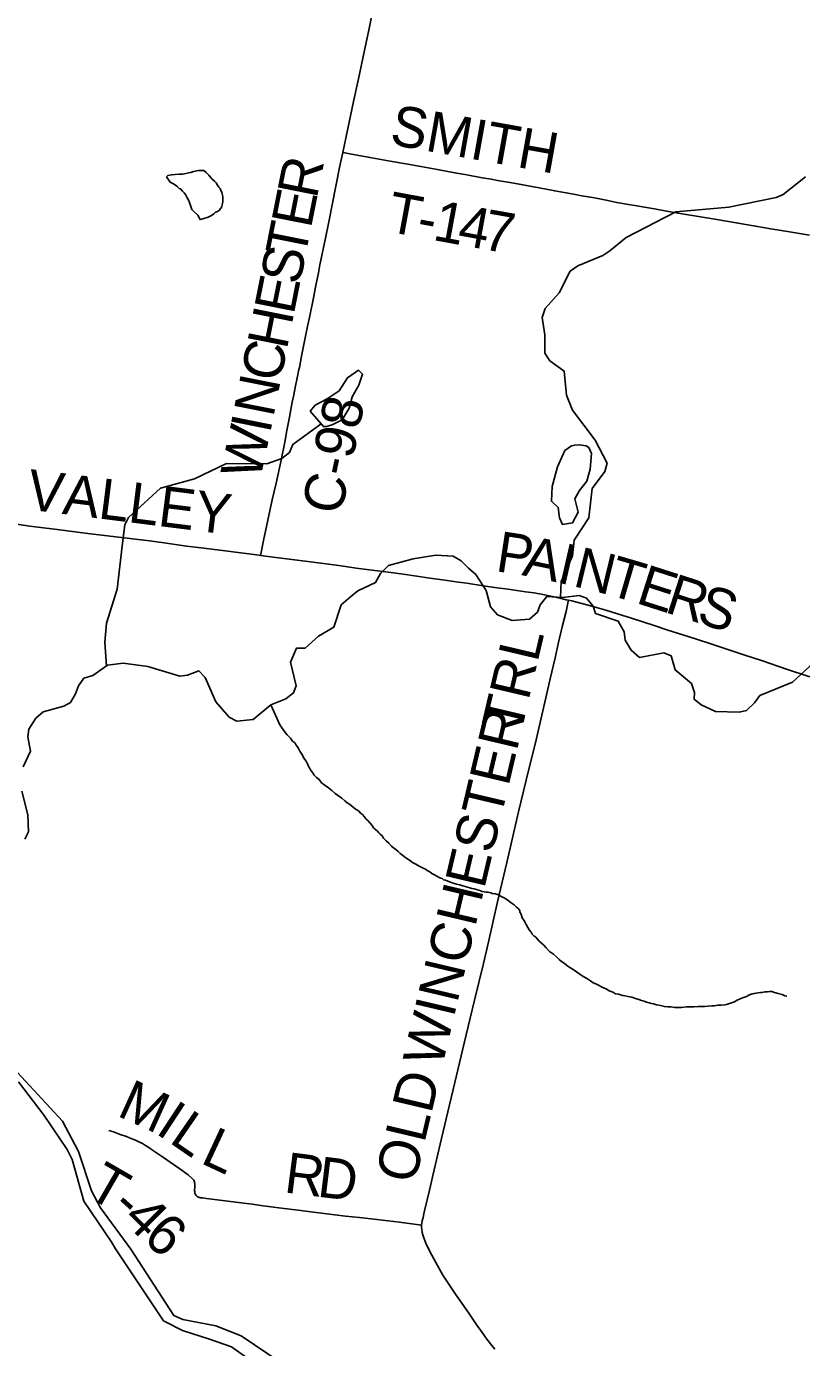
# Model space of a CAD drawing. Extents: x 0 to 34, y 0 to 22.
# Drawn here: x 13.996 to 15.084, y 15.23 to 17.083 of the extents above; entities that cross this region are included whole.
import ezdxf

# ---------------------------------------------------------------- set-up
doc = ezdxf.new("R2010")
doc.units = 0
for name, color, linetype in [('GM_X_County_Road', 7, 'Continuous'), ('GM_X_County_Road_Text', 7, 'Continuous'), ('GM_X_Major_River', 7, 'Continuous'), ('GM_X_Minor_Lake', 7, 'Continuous'), ('GM_X_Minor_River', 7, 'Continuous'), ('GM_X_Township_Road', 7, 'Continuous'), ('GM_X_Township_Road_Text', 7, 'Continuous')]:
    doc.layers.add(name, color=color, linetype=linetype)

msp = doc.modelspace()

# ---------------------------------------------------------------- linework, layer by layer
at = {"layer": 'GM_X_County_Road'}
for points in [[(14.4399, 16.9067), (14.4447, 16.929), (14.455, 16.9779), (14.4618, 17.0101), (14.4699, 17.0477), (14.4764, 17.0781), (14.4788, 17.0897), (14.492, 17.1529), (14.5013, 17.1973), (14.5071, 17.2259), (14.5143, 17.26), (14.5245, 17.3093), (14.5306, 17.3385), (14.5378, 17.3731), (14.5497, 17.4303), (14.5578, 17.468), (14.5635, 17.495), (14.5698, 17.521), (14.5735, 17.5351), (14.5758, 17.5439), (14.5794, 17.557)], [(14.3245, 16.3413), (14.3253, 16.3451), (14.3288, 16.3621), (14.3409, 16.4191), (14.3463, 16.4427), (14.3534, 16.4749), (14.3584, 16.4999), (14.3616, 16.5165), (14.3651, 16.5353), (14.367, 16.5459), (14.3689, 16.5561), (14.3711, 16.5667), (14.3737, 16.5791), (14.3759, 16.5906), (14.3768, 16.5948), (14.378, 16.6002), (14.379, 16.605), (14.3822, 16.6209), (14.3845, 16.6325), (14.3877, 16.6489), (14.3909, 16.6647), (14.3931, 16.675), (14.3986, 16.7024), (14.4022, 16.72), (14.4058, 16.7377), (14.4079, 16.7487), (14.4156, 16.7864), (14.4204, 16.8094), (14.4256, 16.8356), (14.4353, 16.8856), (14.4399, 16.9067)], [(13.8466, 16.4027), (13.8542, 16.4017), (13.8696, 16.3998), (13.8905, 16.397), (13.909, 16.3944), (13.9274, 16.3919), (13.9502, 16.389), (13.9656, 16.3871), (13.9792, 16.3854), (14.0007, 16.3824), (14.0354, 16.378), (14.082, 16.3721), (14.1408, 16.3651), (14.1684, 16.3616), (14.1892, 16.3588), (14.2205, 16.3544), (14.241, 16.3518), (14.2712, 16.348), (14.3225, 16.3416)], [(14.3225, 16.3416), (14.3245, 16.3413), (14.3459, 16.3382), (14.3686, 16.3354), (14.3871, 16.3331), (14.4127, 16.3297), (14.4377, 16.3264), (14.4588, 16.3235), (14.481, 16.3207), (14.5043, 16.3177), (14.5247, 16.3147), (14.5438, 16.312), (14.5622, 16.3095), (14.5801, 16.3069), (14.6022, 16.3037), (14.6139, 16.3021), (14.6372, 16.2987), (14.6569, 16.2959), (14.6721, 16.2938), (14.6842, 16.292), (14.6967, 16.2903), (14.7088, 16.2885), (14.7206, 16.2864), (14.7322, 16.284), (14.7429, 16.2816), (14.7537, 16.2791), (14.7568, 16.2784)], [(14.7568, 16.2784), (14.7614, 16.2773), (14.7739, 16.274), (14.7896, 16.27), (14.8092, 16.2644), (14.8318, 16.2573), (14.8454, 16.253), (14.8773, 16.2427), (14.895, 16.237), (14.9353, 16.224), (14.9579, 16.2166), (14.985, 16.2077), (15.0031, 16.2018), (15.029, 16.1932), (15.0402, 16.1895), (15.0613, 16.1823), (15.0958, 16.171)]]:
    msp.add_lwpolyline(points, dxfattribs=at)
at = {"layer": 'GM_X_Major_River'}
for points in [[(13.9772, 15.6224), (14.0462, 15.5474), (14.0691, 15.5047), (14.0873, 15.4499), (14.0996, 15.4257), (14.1424, 15.3677)], [(13.9847, 15.6028), (14.0205, 15.5556), (14.0532, 15.5077), (14.0598, 15.4939), (14.0763, 15.435), (14.1149, 15.3786), (14.1207, 15.3682), (14.1884, 15.2674), (14.215, 15.2538), (14.2528, 15.2416), (14.2837, 15.231), (14.3536, 15.1811)], [(14.1424, 15.3677), (14.2026, 15.2746), (14.2154, 15.2694), (14.2619, 15.2604), (14.2973, 15.2462), (14.3883, 15.1848)]]:
    msp.add_lwpolyline(points, dxfattribs=at)
at = {"layer": 'GM_X_Minor_Lake'}
for points in [[(14.1925, 16.8723), (14.1929, 16.8727), (14.1944, 16.8742), (14.1994, 16.8753), (14.2047, 16.8757), (14.2104, 16.876), (14.215, 16.8763), (14.2195, 16.8771), (14.2233, 16.8778), (14.2268, 16.8785), (14.2302, 16.8797), (14.2329, 16.8804), (14.2352, 16.8808), (14.2374, 16.8811), (14.2405, 16.8815), (14.2431, 16.8815), (14.245, 16.8815), (14.2481, 16.8784), (14.2518, 16.8746), (14.256, 16.8696), (14.2598, 16.8665), (14.262, 16.8638), (14.2639, 16.8608), (14.2658, 16.8581), (14.2677, 16.8558), (14.2688, 16.8532), (14.2699, 16.8509), (14.2714, 16.8444), (14.2714, 16.8398), (14.2717, 16.8379), (14.271, 16.8349), (14.2706, 16.833), (14.2702, 16.8303), (14.2683, 16.8281), (14.2667, 16.8258), (14.264, 16.8239), (14.2614, 16.8228), (14.2591, 16.8205), (14.2556, 16.8183), (14.2511, 16.8157), (14.245, 16.8138), (14.2419, 16.8131), (14.2396, 16.8123), (14.2363, 16.8184), (14.2306, 16.8238), (14.2279, 16.8265), (14.2268, 16.8307), (14.2253, 16.8348), (14.2242, 16.8379), (14.2235, 16.8398), (14.2212, 16.844), (14.219, 16.8474), (14.2171, 16.8501), (14.2148, 16.8524), (14.2122, 16.8555), (14.2103, 16.8562), (14.2069, 16.8593), (14.2038, 16.8616), (14.2012, 16.8628), (14.1993, 16.8639), (14.1974, 16.8651), (14.1925, 16.8723)], [(14.4262, 16.5249), (14.4393, 16.5315), (14.4491, 16.5476), (14.4529, 16.5638), (14.4623, 16.5799), (14.4676, 16.5954), (14.462, 16.6012), (14.4466, 16.5906), (14.4348, 16.5719), (14.4179, 16.5609), (14.4014, 16.5521), (14.394, 16.5436)], [(14.394, 16.5436), (14.4128, 16.522), (14.4175, 16.522), (14.4262, 16.5249)], [(14.761, 16.4951), (14.7518, 16.4885), (14.7414, 16.4655), (14.734, 16.438), (14.7328, 16.4171), (14.7425, 16.4085), (14.7444, 16.394), (14.7484, 16.3848), (14.7625, 16.3868), (14.7704, 16.4018), (14.7659, 16.4205), (14.7722, 16.4321), (14.7827, 16.4452), (14.7873, 16.4622), (14.7892, 16.4842), (14.7856, 16.4926)], [(14.7856, 16.4926), (14.7815, 16.4949), (14.7722, 16.4965), (14.7657, 16.496), (14.761, 16.4951)]]:
    msp.add_lwpolyline(points, dxfattribs=at)
at = {"layer": 'GM_X_Minor_River'}
for points in [[(14.7454, 16.2824), (14.7467, 16.3047), (14.7627, 16.3408), (14.7646, 16.3624), (14.7854, 16.3938), (14.7901, 16.4351), (14.8077, 16.459), (14.811, 16.4708), (14.7942, 16.5031), (14.7625, 16.5448), (14.7542, 16.5659), (14.7507, 16.5998), (14.7306, 16.6143), (14.7236, 16.6251), (14.7237, 16.6506), (14.7197, 16.675), (14.7242, 16.6878), (14.7436, 16.7094), (14.759, 16.7398), (14.7698, 16.7475), (14.8051, 16.7619), (14.8147, 16.7685), (14.8379, 16.7873), (14.9077, 16.8233), (14.9818, 16.8299), (15.0485, 16.8436), (15.0581, 16.8475), (15.0897, 16.8722)], [(14.1081, 16.1859), (14.1059, 16.2194), (14.108, 16.2463), (14.1234, 16.2938), (14.1305, 16.3582), (14.1341, 16.384), (14.1392, 16.3945), (14.1841, 16.4356), (14.2318, 16.4486), (14.2767, 16.4703), (14.3332, 16.4698), (14.3543, 16.4772), (14.3651, 16.4857), (14.3699, 16.497), (14.4094, 16.5259)], [(13.9914, 16.0446), (14.0017, 16.0664), (13.9979, 16.0867), (13.9993, 16.0973), (14.0091, 16.113), (14.0192, 16.1219), (14.0482, 16.1296), (14.0578, 16.135), (14.0645, 16.147), (14.0689, 16.1583), (14.0764, 16.1692), (14.089, 16.1727), (14.1098, 16.187), (14.1314, 16.1899), (14.1663, 16.1853), (14.2111, 16.1717), (14.2218, 16.173), (14.2378, 16.1795), (14.2467, 16.1698), (14.2619, 16.1356), (14.2805, 16.1143), (14.2913, 16.1087), (14.3142, 16.1108), (14.3389, 16.1315), (14.3599, 16.1401), (14.3707, 16.1482), (14.3744, 16.1584), (14.3667, 16.1913), (14.3751, 16.2112), (14.3869, 16.2113), (14.4058, 16.228), (14.4274, 16.2404), (14.4375, 16.2717), (14.4507, 16.2831), (14.4611, 16.2913), (14.486, 16.3032), (14.4931, 16.316), (14.5043, 16.3271), (14.5387, 16.3365), (14.5707, 16.3415), (14.5949, 16.3402), (14.6062, 16.3338), (14.6166, 16.3233), (14.6266, 16.3144), (14.6413, 16.292), (14.6473, 16.269), (14.6573, 16.2578), (14.6776, 16.2497), (14.7019, 16.2518), (14.7135, 16.2618), (14.7172, 16.272), (14.7265, 16.2835), (14.7489, 16.2823), (14.7717, 16.2848), (14.7822, 16.2811), (14.7915, 16.2699), (14.7947, 16.2599), (14.8267, 16.2489), (14.8351, 16.2339), (14.8364, 16.2221), (14.8448, 16.2082), (14.8567, 16.1981), (14.8906, 16.2045), (14.9008, 16.2004), (14.9068, 16.1809), (14.9296, 16.1614), (14.9339, 16.1491), (14.9333, 16.1393), (14.943, 16.1315), (14.9633, 16.1222), (14.9966, 16.1211), (15.0069, 16.1235), (15.0178, 16.1346), (15.0256, 16.1447), (15.0715, 16.1634), (15.1304, 16.2175)], [(14.3389, 16.1315), (14.3516, 16.1037), (14.3591, 16.0927), (14.3618, 16.0896), (14.3648, 16.0865), (14.3667, 16.085), (14.3693, 16.0808), (14.372, 16.0789), (14.3735, 16.077), (14.3746, 16.0751), (14.3765, 16.0728), (14.378, 16.0701), (14.3795, 16.0667), (14.3814, 16.0636), (14.3833, 16.0609), (14.3848, 16.0579), (14.3866, 16.0548), (14.3885, 16.0525), (14.3904, 16.0487), (14.3912, 16.0464), (14.3923, 16.0445), (14.3938, 16.0422), (14.3945, 16.0403), (14.3975, 16.0365), (14.3998, 16.0331), (14.4032, 16.0296), (14.4066, 16.0269), (14.41, 16.0223), (14.4153, 16.0185), (14.4198, 16.0151), (14.4248, 16.0116), (14.4293, 16.0074), (14.4338, 16.0039), (14.4388, 16.0005), (14.4429, 15.997), (14.4463, 15.9943), (14.4493, 15.9924), (14.4524, 15.9901), (14.4546, 15.9878), (14.458, 15.9851), (14.4607, 15.9836), (14.463, 15.9817), (14.4648, 15.9798), (14.4675, 15.9775), (14.4701, 15.9748), (14.4728, 15.9713), (14.475, 15.9694), (14.4811, 15.9622), (14.4833, 15.9591), (14.4864, 15.9564), (14.4886, 15.9545), (14.4905, 15.9522), (14.4924, 15.9503), (14.4951, 15.948), (14.4973, 15.9446), (14.5007, 15.9407), (14.5045, 15.9373), (14.5083, 15.9334), (14.5113, 15.9308), (14.5143, 15.9288), (14.5177, 15.9258), (14.5207, 15.9231), (14.5241, 15.92), (14.5287, 15.917), (14.5336, 15.9135), (14.5378, 15.9104), (14.5423, 15.9081), (14.5472, 15.9054), (14.551, 15.9035), (14.5537, 15.902), (14.5563, 15.9008), (14.5582, 15.8993), (14.562, 15.8973), (14.565, 15.895), (14.5688, 15.8931), (14.5722, 15.8912), (14.5753, 15.8893), (14.5775, 15.8885), (14.5794, 15.8877), (14.5813, 15.8862), (14.584, 15.8854), (14.5866, 15.8846), (14.5897, 15.8831), (14.595, 15.8815), (14.5995, 15.88), (14.6045, 15.8788), (14.6083, 15.8776), (14.6117, 15.8765), (14.6151, 15.8757), (14.6185, 15.8749), (14.6212, 15.8737), (14.6242, 15.8733), (14.6276, 15.8725), (14.631, 15.8714), (14.6356, 15.8698), (14.6413, 15.8686), (14.6439, 15.8686), (14.6477, 15.8678), (14.6496, 15.8671), (14.6542, 15.8663), (14.6569, 15.8655)], [(13.9934, 15.9432), (13.9985, 15.9533), (13.9979, 15.9772), (13.9895, 16.0105)], [(14.6569, 15.8655), (14.6588, 15.8655), (14.6625, 15.8628), (14.6675, 15.8601), (14.672, 15.857), (14.6765, 15.8539), (14.6807, 15.8509), (14.6837, 15.8478), (14.686, 15.8459), (14.6883, 15.8428), (14.6886, 15.8409), (14.6898, 15.8386), (14.6909, 15.836), (14.692, 15.8325), (14.6943, 15.8295), (14.6961, 15.8264), (14.6973, 15.8234), (14.6999, 15.8192), (14.7018, 15.8157), (14.7044, 15.8127), (14.7059, 15.81), (14.7082, 15.8073), (14.7108, 15.8054), (14.7131, 15.8027), (14.7157, 15.8001), (14.7191, 15.7974), (14.7222, 15.7943), (14.7256, 15.7905), (14.7301, 15.7855), (14.7358, 15.7817), (14.7399, 15.7782), (14.7437, 15.7744), (14.7471, 15.7717), (14.7509, 15.769), (14.7547, 15.7659), (14.7588, 15.7629), (14.7634, 15.7602), (14.7774, 15.7506), (14.7834, 15.7471), (14.7876, 15.7444), (14.7914, 15.7417), (14.7952, 15.7402), (14.799, 15.7383), (14.8024, 15.7363), (14.8058, 15.7344), (14.8096, 15.7329), (14.813, 15.7306), (14.8168, 15.7294), (14.8202, 15.7278), (14.8228, 15.7263), (14.827, 15.7255), (14.8297, 15.7247), (14.8331, 15.7239), (14.8361, 15.7232), (14.8403, 15.7224), (14.8456, 15.7212), (14.8509, 15.7196), (14.8555, 15.7181), (14.8593, 15.7169), (14.8631, 15.7158), (14.8665, 15.7146), (14.8703, 15.7134), (14.8733, 15.7126), (14.8764, 15.7119), (14.8802, 15.7107), (14.884, 15.7103), (14.8878, 15.7095), (14.8915, 15.7083), (14.8961, 15.7079), (14.9007, 15.7079), (14.9056, 15.7071), (14.9105, 15.7071), (14.9155, 15.707), (14.9223, 15.7077), (14.9277, 15.7077), (14.933, 15.708), (14.9387, 15.7084), (14.9436, 15.7083), (14.9482, 15.7083), (14.9531, 15.709), (14.9581, 15.7094), (14.9619, 15.7093), (14.9665, 15.7101), (14.971, 15.7104), (14.9763, 15.7108), (14.9786, 15.7111), (14.9817, 15.7119), (14.9897, 15.7149), (14.9935, 15.7171), (14.9977, 15.719), (15.0011, 15.7205), (15.0038, 15.7216), (15.0057, 15.722), (15.011, 15.7246), (15.0145, 15.7261), (15.0179, 15.7268), (15.0202, 15.7272), (15.0232, 15.7275), (15.0263, 15.7279), (15.0286, 15.7279), (15.0308, 15.7286)], [(15.0308, 15.7286), (15.0327, 15.729), (15.0362, 15.729), (15.0392, 15.7293), (15.0423, 15.7293), (15.046, 15.7281), (15.0514, 15.7266), (15.0567, 15.725), (15.0608, 15.7231), (15.0631, 15.7227), (15.0635, 15.7227)]]:
    msp.add_lwpolyline(points, dxfattribs=at)
at = {"layer": 'GM_X_Township_Road'}
for points in [[(14.4399, 16.9067), (14.4428, 16.9061), (14.4498, 16.9048), (14.4627, 16.9024), (14.4809, 16.8991), (14.5066, 16.8945), (14.5311, 16.8902), (14.5494, 16.887), (14.5751, 16.8822), (14.5973, 16.8782), (14.6142, 16.875), (14.6356, 16.8712), (14.6482, 16.869), (14.6573, 16.8674), (14.6803, 16.8633), (14.7157, 16.8568), (14.7376, 16.8526), (14.7639, 16.8479), (14.7755, 16.8458), (14.7932, 16.8427), (14.8096, 16.8396), (14.8249, 16.8366), (14.8413, 16.8336), (14.853, 16.8317), (14.8634, 16.8299), (14.8777, 16.8273), (14.8946, 16.8244), (14.9166, 16.8204), (14.9649, 16.8127), (14.9924, 16.808), (15.0195, 16.8033), (15.0408, 16.7996), (15.0671, 16.7952), (15.0951, 16.7905)], [(14.5506, 15.4017), (14.5516, 15.4076), (14.5527, 15.4122), (14.5539, 15.4173), (14.5549, 15.4215), (14.5618, 15.4506), (14.5669, 15.473), (14.5715, 15.493), (14.5786, 15.523), (14.59, 15.5706), (14.5972, 15.6016), (14.6102, 15.6569), (14.6188, 15.6921), (14.625, 15.7174), (14.6375, 15.7688), (14.645, 15.8009), (14.6571, 15.855), (14.6704, 15.9102), (14.6867, 15.9815), (14.6975, 16.0258), (14.7113, 16.0824), (14.7234, 16.1354), (14.7311, 16.1682), (14.738, 16.1976), (14.7424, 16.217), (14.7486, 16.2428), (14.7534, 16.2626), (14.7559, 16.274), (14.7568, 16.2784)], [(14.1114, 15.5345), (14.1179, 15.5323), (14.1274, 15.5289), (14.1361, 15.5258), (14.1405, 15.524), (14.1453, 15.5222), (14.1489, 15.5206), (14.1538, 15.5184), (14.1588, 15.5159), (14.163, 15.5134), (14.1675, 15.5104), (14.1728, 15.5067), (14.1868, 15.4973), (14.2039, 15.4859), (14.2113, 15.4805), (14.2227, 15.4722), (14.2284, 15.4672), (14.2295, 15.4662), (14.2301, 15.4655), (14.2306, 15.4646), (14.2311, 15.4635), (14.2316, 15.4622), (14.2319, 15.4612), (14.2321, 15.46), (14.2322, 15.4586), (14.2322, 15.4566), (14.2321, 15.4541), (14.2319, 15.4511), (14.2319, 15.4499), (14.232, 15.4485), (14.2321, 15.4475), (14.2324, 15.4465), (14.2327, 15.4457), (14.2332, 15.4447), (14.2337, 15.4439), (14.2343, 15.4431), (14.235, 15.4422), (14.2356, 15.4416), (14.2363, 15.4411), (14.2373, 15.4407), (14.2381, 15.4404), (14.2391, 15.4402), (14.24, 15.44), (14.2433, 15.4397), (14.2486, 15.439), (14.2973, 15.433), (14.3129, 15.431), (14.3282, 15.4288), (14.354, 15.4255), (14.3773, 15.4225), (14.3989, 15.4198), (14.4211, 15.4169), (14.4439, 15.4143), (14.4636, 15.4121), (14.4878, 15.4095), (14.5198, 15.4056), (14.5506, 15.4017)], [(14.6534, 15.2276), (14.6492, 15.2328), (14.6422, 15.2416), (14.6355, 15.2511), (14.6273, 15.2627), (14.6168, 15.2779), (14.5984, 15.3046), (14.5805, 15.3315), (14.5708, 15.349), (14.562, 15.3648), (14.5564, 15.3761), (14.5536, 15.3836), (14.5523, 15.3878), (14.5515, 15.3913), (14.5507, 15.3961), (14.5505, 15.3988), (14.5506, 15.4017)]]:
    msp.add_lwpolyline(points, dxfattribs=at)

# ---------------------------------------------------------------- texts
at = {"layer": 'GM_X_County_Road_Text'}
for s, height, rotation, p in [('R', 0.0568, 78.6901, (14.4033, 16.8403)), ('E', 0.0568, 78.7556, (14.3951, 16.7987)), ('T', 0.0568, 78.7556, (14.3868, 16.757)), ('S', 0.0568, 78.7548, (14.3793, 16.7194)), ('E', 0.0568, 78.7556, (14.371, 16.6777)), ('H', 0.0568, 78.7594, (14.3613, 16.6287)), ('C', 0.0568, 78.7583, (14.3522, 16.5829)), ('N', 0.0568, 78.7532, (14.3424, 16.5338)), ('C-98', 0.05682, 78.1627, (14.4374, 16.3963)), ('I', 0.0568, 78.694, (14.3378, 16.5109)), ('W', 0.0568, 77.6512, (14.3235, 16.4455)), ('VALLEY', 0.05682, 352.8322, (13.9946, 16.406)), ('P', 0.0568, 351.3696, (14.6531, 16.3193)), ('A', 0.0568, 348.3861, (14.6903, 16.3137)), ('I', 0.0568, 347.1016, (14.7389, 16.3037)), ('N', 0.0568, 346.3039, (14.7615, 16.2985)), ('T', 0.0568, 343.6743, (14.8094, 16.2869)), ('E', 0.0568, 342.2745, (14.8498, 16.275)), ('R', 0.0568, 342.1822, (14.8903, 16.2621)), ('S', 0.0568, 342.1814, (14.9347, 16.2478))]:
    msp.add_text(s, height=height, rotation=rotation, dxfattribs=at).set_placement(p)
at = {"layer": 'GM_X_Township_Road_Text'}
for s, height, rotation, p in [('SMITH', 0.05682, 349.8511, (14.5043, 16.9183)), ('T', 0.0568, 349.497, (14.5, 16.7961)), ('1', 0.0568, 349.5223, (14.5647, 16.7841)), ('-', 0.0568, 349.5115, (14.5418, 16.7883)), ('4', 0.0568, 349.6238, (14.5993, 16.7777)), ('7', 0.0568, 349.9745, (14.6341, 16.7713)), ('TRL', 0.05682, 76.7539, (14.69, 16.0913)), ('WINCHESTER', 0.05682, 76.6941, (14.5792, 15.6216)), ('OLD', 0.05682, 76.6822, (14.5408, 15.458)), ('M', 0.0568, 335.5211, (14.1213, 15.5557)), ('I', 0.0568, 326.717, (14.1754, 15.5312)), ('L', 0.0568, 325.4286, (14.1946, 15.5186)), ('L', 0.0568, 335.0031, (14.2385, 15.4894)), ('R', 0.0568, 352.6813, (14.3562, 15.4478)), ('D', 0.0568, 352.9654, (14.4028, 15.4418)), ('T', 0.0568, 329.9848, (14.0782, 15.4433)), ('-', 0.0568, 318.1172, (14.1125, 15.4239)), ('4', 0.0568, 314.7719, (14.1292, 15.4089)), ('6', 0.0568, 319.3704, (14.1575, 15.3807))]:
    msp.add_text(s, height=height, rotation=rotation, dxfattribs=at).set_placement(p)

doc.saveas('drawing.dxf')
